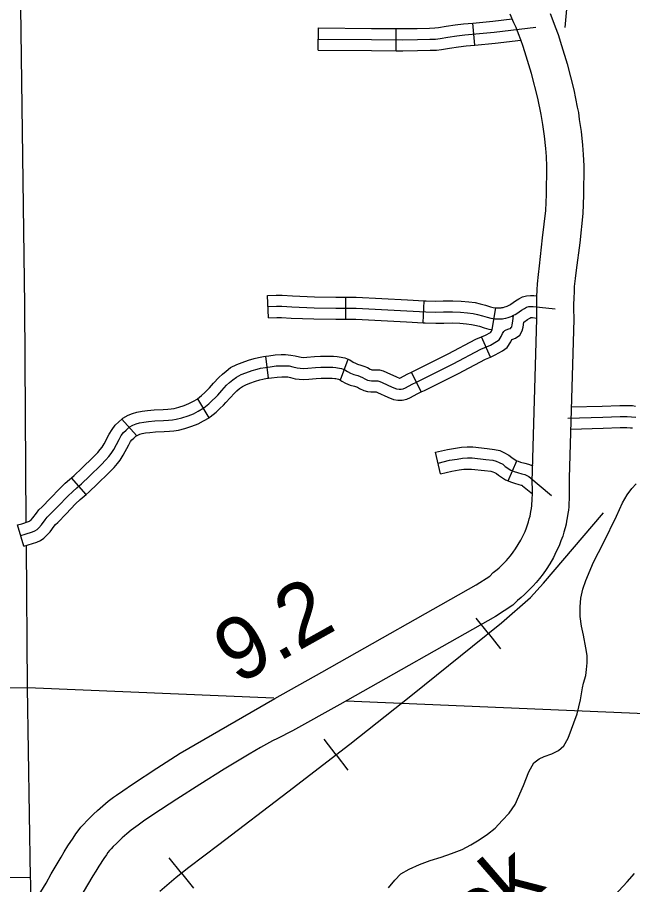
# Model space of a CAD drawing. Extents: x -3711 to 825, y -151 to 1050.
# Drawn here: x -2836.4 to -2789.6, y 186.7 to 252.6 of the extents above; entities that cross this region are included whole.
import ezdxf

# ---------------------------------------------------------------- set-up
doc = ezdxf.new("R2010")
doc.units = 0
for name, color, linetype in [('Level 10', 7, 'Continuous'), ('Level 31', 7, 'Continuous'), ('Level 32', 7, 'Continuous'), ('Level 35', 7, 'Continuous'), ('Level 38', 7, 'Continuous'), ('Level 40', 7, 'Continuous'), ('Level 48', 7, 'Continuous'), ('Level 5', 7, 'Continuous'), ('Level 6', 7, 'Continuous')]:
    doc.layers.add(name, color=color, linetype=linetype)

msp = doc.modelspace()

# ---------------------------------------------------------------- linework, layer by layer
at = {"layer": 'Level 10'}
for points in [[(-2796.887, 229.683), (-2796.9, 230.43), (-2796.903, 230.794), (-2796.885, 231.371), (-2796.87, 231.883), (-2796.84, 232.354), (-2796.776, 233.061), (-2796.687, 233.729), (-2796.454, 235.844), (-2796.2, 237.917), (-2796.148, 239.145), (-2796.134, 241.27), (-2796.168, 242.016), (-2796.212, 242.644), (-2796.318, 243.585), (-2796.44, 244.454), (-2796.506, 244.908), (-2796.566, 245.227), (-2796.822, 246.454), (-2797.294, 248.33), (-2797.692, 249.647), (-2797.923, 250.393), (-2798.111, 250.893), (-2798.286, 251.348), (-2798.473, 251.822), (-2798.634, 252.193), (-2798.918, 252.84)], [(-2795.885, 252.896), (-2795.675, 252.366), (-2795.491, 251.887), (-2795.271, 251.301), (-2795.012, 250.468), (-2794.593, 249.076), (-2794.091, 247.082), (-2793.818, 245.775), (-2793.741, 245.37), (-2793.666, 244.849), (-2793.538, 243.937), (-2793.421, 242.9), (-2793.37, 242.177), (-2793.332, 241.323), (-2793.346, 239.076), (-2793.405, 237.701), (-2793.634, 235.468), (-2793.908, 233.377), (-2793.991, 232.751), (-2794.046, 232.14), (-2794.07, 231.753), (-2794.084, 231.286), (-2794.1, 230.762), (-2794.098, 230.464), (-2794.084, 229.666)], [(-2797.241, 217.309), (-2796.887, 229.683)], [(-2794.084, 229.666), (-2794.43, 217.591)], [(-2794.43, 217.591), (-2794.43, 216.488), (-2794.43, 216.204), (-2794.439, 215.976), (-2794.454, 215.692), (-2794.469, 215.402), (-2794.501, 215.148), (-2794.533, 214.896), (-2794.58, 214.566), (-2794.63, 214.316), (-2794.674, 214.092), (-2794.747, 213.8), (-2794.832, 213.469), (-2794.928, 213.174), (-2795.068, 212.807), (-2795.206, 212.436), (-2795.415, 211.995), (-2795.637, 211.545), (-2795.903, 211.081), (-2796.194, 210.626), (-2796.415, 210.316), (-2796.681, 209.958), (-2796.943, 209.638), (-2797.168, 209.387), (-2797.526, 209.031), (-2797.835, 208.733), (-2798.085, 208.503), (-2798.357, 208.288), (-2798.72, 207.939), (-2800.04, 207.077), (-2811.86, 200.381), (-2815.449, 198.388)], [(-2816.809, 200.837), (-2813.231, 202.824), (-2801.498, 209.472), (-2800.472, 210.142), (-2800.201, 210.402), (-2799.906, 210.635), (-2799.757, 210.773), (-2799.485, 211.034), (-2799.201, 211.317), (-2799.071, 211.462), (-2798.891, 211.682), (-2798.681, 211.965), (-2798.516, 212.196), (-2798.301, 212.532), (-2798.111, 212.863), (-2797.937, 213.215), (-2797.791, 213.526), (-2797.69, 213.796), (-2797.571, 214.108), (-2797.524, 214.251), (-2797.464, 214.487), (-2797.409, 214.704), (-2797.378, 214.861), (-2797.343, 215.04), (-2797.31, 215.27), (-2797.281, 215.498), (-2797.262, 215.651), (-2797.252, 215.839), (-2797.238, 216.102), (-2797.232, 216.256), (-2797.232, 216.488), (-2797.232, 216.726), (-2797.241, 217.309)], [(-2834.781, 185.813), (-2834.179, 186.791), (-2833.783, 187.504), (-2833.029, 188.782), (-2832.796, 189.176), (-2832.516, 189.624), (-2832.11, 190.229), (-2831.905, 190.538), (-2831.735, 190.78), (-2831.528, 191.05), (-2831.319, 191.287), (-2831.083, 191.54), (-2830.781, 191.834), (-2830.564, 192.045), (-2830.274, 192.319), (-2829.861, 192.68), (-2829.449, 193.02), (-2829.047, 193.326), (-2828.832, 193.486), (-2828.353, 193.824), (-2827.615, 194.322), (-2825.766, 195.527), (-2823.983, 196.675), (-2816.809, 200.837)], [(-2815.449, 198.388), (-2816.586, 197.805), (-2816.965, 197.612), (-2817.876, 197.103), (-2818.741, 196.598), (-2820.656, 195.454), (-2822.5, 194.297), (-2824.243, 193.175), (-2826.067, 191.986), (-2826.762, 191.518), (-2827.189, 191.217), (-2827.361, 191.088), (-2827.707, 190.824), (-2828.048, 190.543), (-2828.389, 190.246), (-2828.623, 190.024), (-2828.827, 189.825), (-2829.082, 189.578), (-2829.242, 189.406), (-2829.36, 189.272), (-2829.475, 189.122), (-2829.591, 188.957), (-2829.78, 188.672), (-2830.164, 188.101), (-2830.401, 187.721), (-2830.617, 187.356), (-2831.352, 186.111)]]:
    msp.add_lwpolyline(points, dxfattribs=at)
at = {"layer": 'Level 31'}
msp.add_lwpolyline([(-2793.495, 183.253), (-2791.659, 185.153), (-2790.026, 186.902), (-2789.483, 187.534)], dxfattribs=at)
at = {"layer": 'Level 32'}
for p, q in [((-2801.611, 250.498), (-2801.765, 252.172)), ((-2813.506, 250.117), (-2813.489, 251.798)), ((-2807.585, 250.065), (-2807.575, 251.746)), ((-2817.28, 229.776), (-2817.344, 231.456)), ((-2811.391, 229.658), (-2811.405, 231.339)), ((-2805.531, 229.391), (-2805.444, 231.07)), ((-2800.288, 228.871), (-2800.021, 230.532)), ((-2800.418, 226.781), (-2801.097, 228.319)), ((-2817.277, 225.183), (-2817.492, 226.85)), ((-2811.82, 225.044), (-2811.221, 226.615)), ((-2805.68, 224.129), (-2806.404, 225.647)), ((-2821.795, 222.177), (-2822.655, 223.621)), ((-2827.306, 220.812), (-2828.431, 222.061)), ((-2804.206, 217.913), (-2804.593, 219.549)), ((-2799.083, 217.369), (-2798.409, 218.909)), ((-2831.131, 216.345), (-2832.236, 217.613)), ((-2835.865, 212.411), (-2836.336, 214.025))]:
    msp.add_line(p, q, dxfattribs=at)
for points in [[(-2801.765, 252.172), (-2800.227, 252.314), (-2798.764, 252.489)], [(-2813.497, 250.957), (-2809.46, 250.916), (-2807.064, 250.902), (-2805.969, 250.916), (-2805.011, 250.943), (-2804.587, 250.957), (-2804.245, 250.998), (-2803.656, 251.094), (-2802.972, 251.19), (-2802.37, 251.272), (-2800.139, 251.478), (-2796.98, 251.857)], [(-2807.575, 251.746), (-2807.067, 251.743), (-2805.987, 251.756), (-2805.037, 251.784), (-2804.651, 251.796), (-2804.363, 251.831), (-2803.782, 251.925), (-2803.087, 252.023), (-2802.465, 252.108), (-2801.765, 252.172)], [(-2813.489, 251.798), (-2809.453, 251.757), (-2807.575, 251.746)], [(-2807.585, 250.065), (-2807.062, 250.062), (-2805.952, 250.076), (-2804.986, 250.103), (-2804.523, 250.118), (-2804.127, 250.166), (-2803.53, 250.263), (-2802.857, 250.357), (-2802.274, 250.437), (-2801.611, 250.498)], [(-2801.611, 250.498), (-2800.05, 250.642), (-2798.104, 250.875)], [(-2813.506, 250.117), (-2809.466, 250.075), (-2807.585, 250.065)], [(-2817.344, 231.456), (-2816.69, 231.481), (-2816.228, 231.481), (-2815.464, 231.431), (-2813.774, 231.37), (-2812.159, 231.333), (-2811.405, 231.339)], [(-2799.669, 230.528), (-2799.604, 230.531), (-2799.555, 230.539), (-2799.453, 230.56), (-2799.321, 230.597), (-2799.216, 230.63), (-2799.152, 230.658), (-2799.047, 230.708), (-2798.956, 230.758), (-2798.873, 230.807), (-2798.521, 231.05), (-2798.25, 231.216), (-2797.983, 231.349), (-2797.668, 231.447), (-2797.382, 231.469), (-2797.133, 231.469), (-2796.883, 231.442)], [(-2811.405, 231.339), (-2810.61, 231.346), (-2806.716, 231.135), (-2805.444, 231.07)], [(-2805.444, 231.07), (-2805.3, 231.062), (-2804.557, 231.038), (-2804, 231.05), (-2803.286, 231.063), (-2802.639, 231.037), (-2802.067, 230.985), (-2801.581, 230.929), (-2801.204, 230.842), (-2800.785, 230.734), (-2800.411, 230.609), (-2800.221, 230.557), (-2800.021, 230.532), (-2799.774, 230.523), (-2799.669, 230.528)], [(-2817.312, 230.616), (-2816.673, 230.64), (-2816.256, 230.64), (-2815.506, 230.591), (-2813.799, 230.53), (-2812.165, 230.493), (-2810.629, 230.505), (-2806.76, 230.296), (-2805.335, 230.222), (-2804.561, 230.198), (-2803.984, 230.21), (-2803.296, 230.222), (-2802.694, 230.198), (-2802.153, 230.148), (-2801.723, 230.099), (-2801.404, 230.025), (-2801.023, 229.927), (-2800.655, 229.804), (-2800.384, 229.73), (-2800.09, 229.694), (-2799.77, 229.681), (-2799.512, 229.694), (-2799.399, 229.713), (-2799.254, 229.743), (-2799.081, 229.792), (-2798.923, 229.841), (-2798.803, 229.893), (-2798.664, 229.959), (-2798.539, 230.028), (-2798.419, 230.099), (-2798.063, 230.345), (-2797.842, 230.48), (-2797.67, 230.566), (-2797.51, 230.616), (-2797.35, 230.628), (-2797.178, 230.628), (-2795.499, 230.447)], [(-2817.28, 229.776), (-2816.657, 229.8), (-2816.283, 229.8), (-2815.549, 229.751), (-2813.823, 229.689), (-2812.171, 229.652), (-2811.391, 229.658)], [(-2811.391, 229.658), (-2810.649, 229.664), (-2806.804, 229.457), (-2805.531, 229.391)], [(-2800.423, 227.697), (-2799.955, 227.956), (-2799.761, 228.101), (-2799.6, 228.344), (-2799.503, 228.57), (-2799.452, 228.66), (-2799.39, 228.731), (-2799.315, 228.798), (-2799.229, 228.845), (-2799.019, 228.925), (-2798.907, 228.967), (-2798.833, 229.02), (-2798.796, 229.089), (-2798.764, 229.221), (-2798.722, 229.518), (-2798.664, 229.959)], [(-2800.418, 226.781), (-2800.05, 226.943), (-2799.497, 227.248), (-2799.142, 227.515), (-2798.858, 227.942), (-2798.783, 228.115), (-2798.72, 228.139), (-2798.509, 228.219), (-2798.185, 228.45), (-2798.004, 228.787), (-2797.938, 229.064), (-2797.883, 229.448)], [(-2797.883, 229.448), (-2797.604, 229.64), (-2797.433, 229.745), (-2797.356, 229.784), (-2797.352, 229.785), (-2797.318, 229.787), (-2797.223, 229.787), (-2796.888, 229.751)], [(-2805.531, 229.391), (-2805.37, 229.382), (-2804.565, 229.357), (-2803.967, 229.369), (-2803.305, 229.381), (-2802.749, 229.359), (-2802.239, 229.312), (-2801.866, 229.269), (-2801.604, 229.209), (-2801.262, 229.12), (-2800.898, 228.999), (-2800.548, 228.904), (-2800.288, 228.871)], [(-2801.097, 228.319), (-2800.797, 228.451), (-2800.413, 228.663), (-2800.381, 228.687), (-2800.342, 228.745), (-2800.288, 228.871)], [(-2806.404, 225.647), (-2806.159, 225.764), (-2803.621, 227.028), (-2801.517, 228.134), (-2801.097, 228.319)], [(-2836.1, 213.218), (-2835.774, 213.313), (-2835.203, 213.492), (-2835.024, 213.582), (-2834.863, 213.689), (-2834.72, 213.814), (-2834.523, 214.029), (-2834.237, 214.422), (-2834.09, 214.615), (-2833.88, 214.813), (-2833.262, 215.443), (-2832.528, 216.213), (-2832.155, 216.574), (-2831.84, 216.843), (-2831.479, 217.158), (-2830.873, 217.729), (-2829.998, 218.581), (-2829.626, 218.966), (-2829.404, 219.222), (-2829.241, 219.444), (-2829.031, 219.747), (-2828.635, 220.529), (-2828.46, 220.82), (-2828.297, 221.042), (-2828.087, 221.24), (-2827.854, 221.45), (-2827.574, 221.614), (-2827.341, 221.707), (-2827.073, 221.789), (-2826.747, 221.847), (-2826.385, 221.894), (-2825.907, 221.94), (-2825.243, 221.964), (-2824.87, 221.987), (-2824.579, 222.01), (-2824.287, 222.057), (-2823.856, 222.162), (-2823.39, 222.313), (-2822.982, 222.477), (-2822.621, 222.663), (-2822.189, 222.92), (-2821.814, 223.24), (-2821.546, 223.479), (-2821.298, 223.718), (-2821.14, 223.888), (-2820.826, 224.25), (-2820.464, 224.646), (-2820.231, 224.856), (-2819.987, 225.055), (-2819.707, 225.265), (-2819.346, 225.451), (-2818.996, 225.58), (-2818.53, 225.755), (-2818.145, 225.871), (-2817.877, 225.93), (-2817.516, 226), (-2817.154, 226.046), (-2816.688, 226.105), (-2816.292, 226.128), (-2816.024, 226.128), (-2815.697, 226.105), (-2815.429, 226.046), (-2815.091, 225.965), (-2814.87, 225.93), (-2814.614, 225.918), (-2814.287, 225.941), (-2813.716, 226), (-2813.296, 226.023), (-2812.9, 226.023), (-2812.387, 226.011), (-2812.154, 225.988), (-2812.038, 225.976), (-2811.723, 225.906), (-2811.478, 225.813), (-2811.268, 225.685), (-2811.047, 225.556), (-2810.791, 225.451), (-2810.499, 225.37), (-2810.313, 225.311), (-2810.138, 225.241), (-2809.963, 225.136), (-2809.753, 225.031), (-2809.613, 224.996), (-2809.462, 224.985), (-2809.136, 224.985), (-2808.984, 224.973), (-2808.832, 224.938), (-2808.646, 224.856), (-2807.888, 224.506), (-2807.55, 224.378), (-2807.364, 224.343), (-2807.201, 224.343), (-2807.038, 224.378), (-2806.869, 224.455), (-2806.362, 224.732), (-2806.047, 224.886), (-2805.79, 225.008), (-2803.238, 226.28), (-2801.152, 227.376), (-2800.423, 227.697)], [(-2822.68, 223.606), (-2822.366, 223.874), (-2822.118, 224.096), (-2821.898, 224.307), (-2821.766, 224.45), (-2821.454, 224.809), (-2821.058, 225.243), (-2820.778, 225.496), (-2820.504, 225.718), (-2820.155, 225.979), (-2819.685, 226.222), (-2819.288, 226.368), (-2818.8, 226.551), (-2818.357, 226.685), (-2818.046, 226.753), (-2817.65, 226.83), (-2817.492, 226.85)], [(-2817.492, 226.85), (-2817.26, 226.88), (-2816.765, 226.942), (-2816.317, 226.969), (-2815.994, 226.969), (-2815.578, 226.939), (-2815.241, 226.866), (-2814.927, 226.79), (-2814.785, 226.767), (-2814.624, 226.76), (-2814.36, 226.779), (-2813.782, 226.838), (-2813.32, 226.864), (-2812.891, 226.864), (-2812.336, 226.851), (-2812.071, 226.824), (-2811.904, 226.808), (-2811.481, 226.714), (-2811.221, 226.615)], [(-2805.68, 224.129), (-2805.422, 224.253), (-2802.855, 225.531), (-2800.786, 226.619), (-2800.418, 226.781)], [(-2811.221, 226.615), (-2811.106, 226.571), (-2810.838, 226.407), (-2810.675, 226.312), (-2810.517, 226.248), (-2810.26, 226.176), (-2810.031, 226.104), (-2809.763, 225.997), (-2809.558, 225.874), (-2809.467, 225.828), (-2809.43, 225.825), (-2809.103, 225.825), (-2808.856, 225.806), (-2808.567, 225.74), (-2808.301, 225.623), (-2807.563, 225.282), (-2807.322, 225.191), (-2807.294, 225.185), (-2807.245, 225.208), (-2806.748, 225.479), (-2806.412, 225.643), (-2806.404, 225.647)], [(-2821.795, 222.177), (-2821.699, 222.234), (-2821.261, 222.607), (-2820.975, 222.863), (-2820.697, 223.129), (-2820.515, 223.327), (-2820.198, 223.691), (-2819.871, 224.05), (-2819.685, 224.217), (-2819.47, 224.392), (-2819.259, 224.55), (-2819.007, 224.68), (-2818.703, 224.792), (-2818.26, 224.958), (-2817.933, 225.057), (-2817.708, 225.106), (-2817.382, 225.169), (-2817.277, 225.183)], [(-2817.277, 225.183), (-2817.048, 225.212), (-2816.611, 225.267), (-2816.267, 225.287), (-2816.054, 225.287), (-2815.817, 225.27), (-2815.617, 225.227), (-2815.256, 225.14), (-2814.955, 225.092), (-2814.603, 225.076), (-2814.214, 225.104), (-2813.65, 225.161), (-2813.273, 225.182), (-2812.91, 225.182), (-2812.439, 225.172), (-2812.238, 225.151), (-2812.171, 225.145), (-2811.965, 225.099), (-2811.82, 225.044)], [(-2811.85, 225.055), (-2811.699, 224.962), (-2811.419, 224.8), (-2811.064, 224.655), (-2810.738, 224.564), (-2810.595, 224.519), (-2810.513, 224.486), (-2810.368, 224.399), (-2810.047, 224.238), (-2809.749, 224.164), (-2809.494, 224.144), (-2809.168, 224.144), (-2809.112, 224.14), (-2809.098, 224.137), (-2808.991, 224.09), (-2808.214, 223.731), (-2807.779, 223.566), (-2807.442, 223.503), (-2807.112, 223.503), (-2806.772, 223.575), (-2806.492, 223.703), (-2805.976, 223.985), (-2805.681, 224.129), (-2805.68, 224.129)], [(-2828.431, 222.061), (-2828.352, 222.133), (-2827.944, 222.371), (-2827.62, 222.501), (-2827.27, 222.607), (-2826.875, 222.678), (-2826.48, 222.729), (-2825.963, 222.779), (-2825.284, 222.803), (-2824.93, 222.825), (-2824.679, 222.845), (-2824.454, 222.882), (-2824.086, 222.971), (-2823.676, 223.104), (-2823.332, 223.242), (-2823.029, 223.399), (-2822.655, 223.621)], [(-2789.407, 223.037), (-2789.632, 223.065), (-2790.014, 223.089), (-2790.595, 223.089), (-2791.921, 223.027), (-2794.276, 222.972)], [(-2827.355, 220.768), (-2827.204, 220.856), (-2827.062, 220.913), (-2826.876, 220.97), (-2826.619, 221.016), (-2826.291, 221.058), (-2825.852, 221.101), (-2825.202, 221.124), (-2824.81, 221.148), (-2824.479, 221.175), (-2824.121, 221.232), (-2823.626, 221.353), (-2823.103, 221.523), (-2822.632, 221.711), (-2822.212, 221.928), (-2821.795, 222.177)], [(-2789.382, 222.187), (-2789.711, 222.228), (-2790.04, 222.249), (-2790.575, 222.249), (-2791.892, 222.187), (-2794.546, 222.125)], [(-2832.236, 217.613), (-2832.043, 217.78), (-2831.454, 218.336), (-2830.594, 219.174), (-2830.246, 219.533), (-2830.062, 219.747), (-2829.925, 219.932), (-2829.755, 220.178), (-2829.371, 220.935), (-2829.161, 221.287), (-2828.929, 221.601), (-2828.657, 221.858), (-2828.431, 222.061)], [(-2789.615, 221.369), (-2789.789, 221.391), (-2790.066, 221.408), (-2790.555, 221.408), (-2791.862, 221.347), (-2794.324, 221.289)], [(-2831.131, 216.345), (-2830.914, 216.535), (-2830.291, 217.122), (-2829.403, 217.987), (-2829.005, 218.398), (-2828.746, 218.698), (-2828.557, 218.955), (-2828.307, 219.316), (-2827.899, 220.122), (-2827.759, 220.354), (-2827.665, 220.483), (-2827.517, 220.622), (-2827.306, 220.812)], [(-2804.593, 219.549), (-2803.688, 219.763), (-2803.069, 219.863), (-2802.622, 219.935), (-2802.19, 219.954), (-2801.76, 219.954), (-2800.676, 219.837), (-2800.099, 219.767), (-2799.712, 219.676), (-2799.39, 219.538), (-2799.011, 219.337), (-2798.787, 219.151), (-2798.457, 218.93), (-2798.409, 218.909)], [(-2804.399, 218.731), (-2803.524, 218.938), (-2802.935, 219.034), (-2802.537, 219.097), (-2802.171, 219.113), (-2801.805, 219.113), (-2800.771, 219.002), (-2800.246, 218.938), (-2799.976, 218.874), (-2799.753, 218.779), (-2799.482, 218.635), (-2799.291, 218.476), (-2798.862, 218.19), (-2798.607, 218.078), (-2798.353, 217.998), (-2798.034, 217.919), (-2797.812, 217.855), (-2797.652, 217.791), (-2797.493, 217.696), (-2795.77, 216.264)], [(-2798.409, 218.909), (-2798.312, 218.867), (-2798.125, 218.808), (-2797.817, 218.731), (-2797.539, 218.652), (-2797.207, 218.519)], [(-2804.206, 217.913), (-2803.36, 218.113), (-2802.801, 218.204), (-2802.452, 218.26), (-2802.153, 218.273), (-2801.851, 218.273), (-2800.867, 218.167), (-2800.393, 218.109), (-2800.24, 218.073), (-2800.116, 218.02), (-2799.953, 217.934), (-2799.795, 217.802), (-2799.267, 217.449), (-2799.083, 217.369)], [(-2836.336, 214.025), (-2836.018, 214.118), (-2835.518, 214.274), (-2835.447, 214.31), (-2835.375, 214.358), (-2835.309, 214.416), (-2835.175, 214.561), (-2834.911, 214.926), (-2834.715, 215.18), (-2834.469, 215.413), (-2833.866, 216.027), (-2833.125, 216.805), (-2832.721, 217.197), (-2832.389, 217.479), (-2832.236, 217.613)], [(-2799.083, 217.369), (-2798.902, 217.29), (-2798.58, 217.189), (-2798.252, 217.107), (-2798.084, 217.059), (-2798.027, 217.036), (-2797.981, 217.008), (-2797.232, 216.386)], [(-2835.865, 212.411), (-2835.531, 212.509), (-2834.887, 212.71), (-2834.601, 212.853), (-2834.351, 213.02), (-2834.131, 213.212), (-2833.871, 213.496), (-2833.564, 213.919), (-2833.464, 214.049), (-2833.291, 214.213), (-2832.658, 214.858), (-2831.931, 215.621), (-2831.589, 215.952), (-2831.291, 216.206), (-2831.131, 216.345)]]:
    msp.add_lwpolyline(points, dxfattribs=at)
at = {"layer": 'Level 35'}
for points in [[(-2793.182, 209.807), (-2792.6, 211.186), (-2791.842, 212.663), (-2790.833, 214.703), (-2790.386, 215.714), (-2790.037, 216.316), (-2789.687, 216.782), (-2789.338, 217.151)], [(-2808.172, 186.451), (-2807.686, 187.034), (-2807.22, 187.5), (-2806.599, 187.85), (-2805.803, 188.219), (-2805.007, 188.51), (-2804.172, 188.782), (-2803.376, 189.054), (-2802.56, 189.365), (-2801.9, 189.715), (-2801.279, 190.084), (-2800.638, 190.531), (-2800.055, 190.978), (-2799.531, 191.561), (-2799.007, 192.125), (-2798.541, 192.785), (-2797.9, 194.223), (-2797.492, 195.253), (-2797.124, 195.933), (-2796.716, 196.244), (-2796.347, 196.438), (-2795.764, 196.632), (-2795.26, 196.885), (-2794.852, 197.235), (-2794.502, 197.818), (-2793.823, 199.664), (-2793.57, 200.732), (-2793.434, 201.646), (-2793.337, 201.995), (-2793.163, 202.578), (-2793.124, 203.045), (-2793.066, 203.55), (-2793.066, 204.094), (-2793.163, 204.677), (-2793.357, 205.648), (-2793.512, 206.328), (-2793.609, 207.067), (-2793.609, 207.805), (-2793.551, 208.466), (-2793.396, 209.146), (-2793.182, 209.807)]]:
    msp.add_lwpolyline(points, dxfattribs=at)
at = {"layer": 'Level 38'}
msp.add_lwpolyline([(-2794.61, 253.501), (-2794.769, 251.828)], dxfattribs=at)
at = {"layer": 'Level 40'}
for p, q in [((-2800.576, 205.777), (-2801.499, 206.933)), ((-2800.576, 205.777), (-2799.653, 204.621)), ((-2812.15, 196.563), (-2813.052, 197.736)), ((-2812.15, 196.563), (-2811.249, 195.39)), ((-2823.898, 187.571), (-2824.818, 188.729)), ((-2823.898, 187.571), (-2822.977, 186.412))]:
    msp.add_line(p, q, dxfattribs=at)
msp.add_lwpolyline([(-2825.53, 186.187), (-2824.296, 187.255), (-2823.341, 188.013), (-2821.04, 189.726), (-2815.821, 193.742), (-2811.107, 197.365), (-2806.336, 201.128), (-2801.79, 204.808), (-2799.574, 206.577), (-2797.385, 208.515), (-2796.375, 209.61), (-2791.829, 214.946)], dxfattribs=at)
msp.add_lwpolyline([(-2825.53, 186.187), (-2824.296, 187.255), (-2823.341, 188.013), (-2821.04, 189.726), (-2815.821, 193.742), (-2811.107, 197.365), (-2806.336, 201.128), (-2801.79, 204.808), (-2799.574, 206.577), (-2797.385, 208.515), (-2796.375, 209.61), (-2791.829, 214.946)], dxfattribs=at)
at = {"layer": 'Level 5'}
for points in [[(-2835.676, 214.207), (-2835.801, 230.734), (-2836.201, 260.947)], [(-2835.349, 187.231), (-2835.582, 201.68), (-2835.663, 212.419)], [(-2845.879, 201.616), (-2835.582, 201.68), (-2816.881, 200.887)], [(-2811.379, 200.653), (-2779.711, 199.309)]]:
    msp.add_lwpolyline(points, dxfattribs=at)
at = {"layer": 'Level 6'}
msp.add_lwpolyline([(-2835.314, 185.067), (-2835.343, 186.875), (-2835.349, 187.231), (-2864.533, 186.829)], dxfattribs=at)

# ---------------------------------------------------------------- texts
at = {"layer": 'Level 35'}
msp.add_text('Creek', height=4.7343, rotation=40.90795, dxfattribs=at).set_placement((-2808.876, 175.429))
at = {"layer": 'Level 48'}
msp.add_text('9.2', height=4.7343, rotation=29.31664, dxfattribs=at).set_placement((-2819.639, 201.83))

doc.saveas('drawing.dxf')
